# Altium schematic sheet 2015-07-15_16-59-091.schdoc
size 405 x 220 mm; SheetNumber: 1; SheetTotal: 1
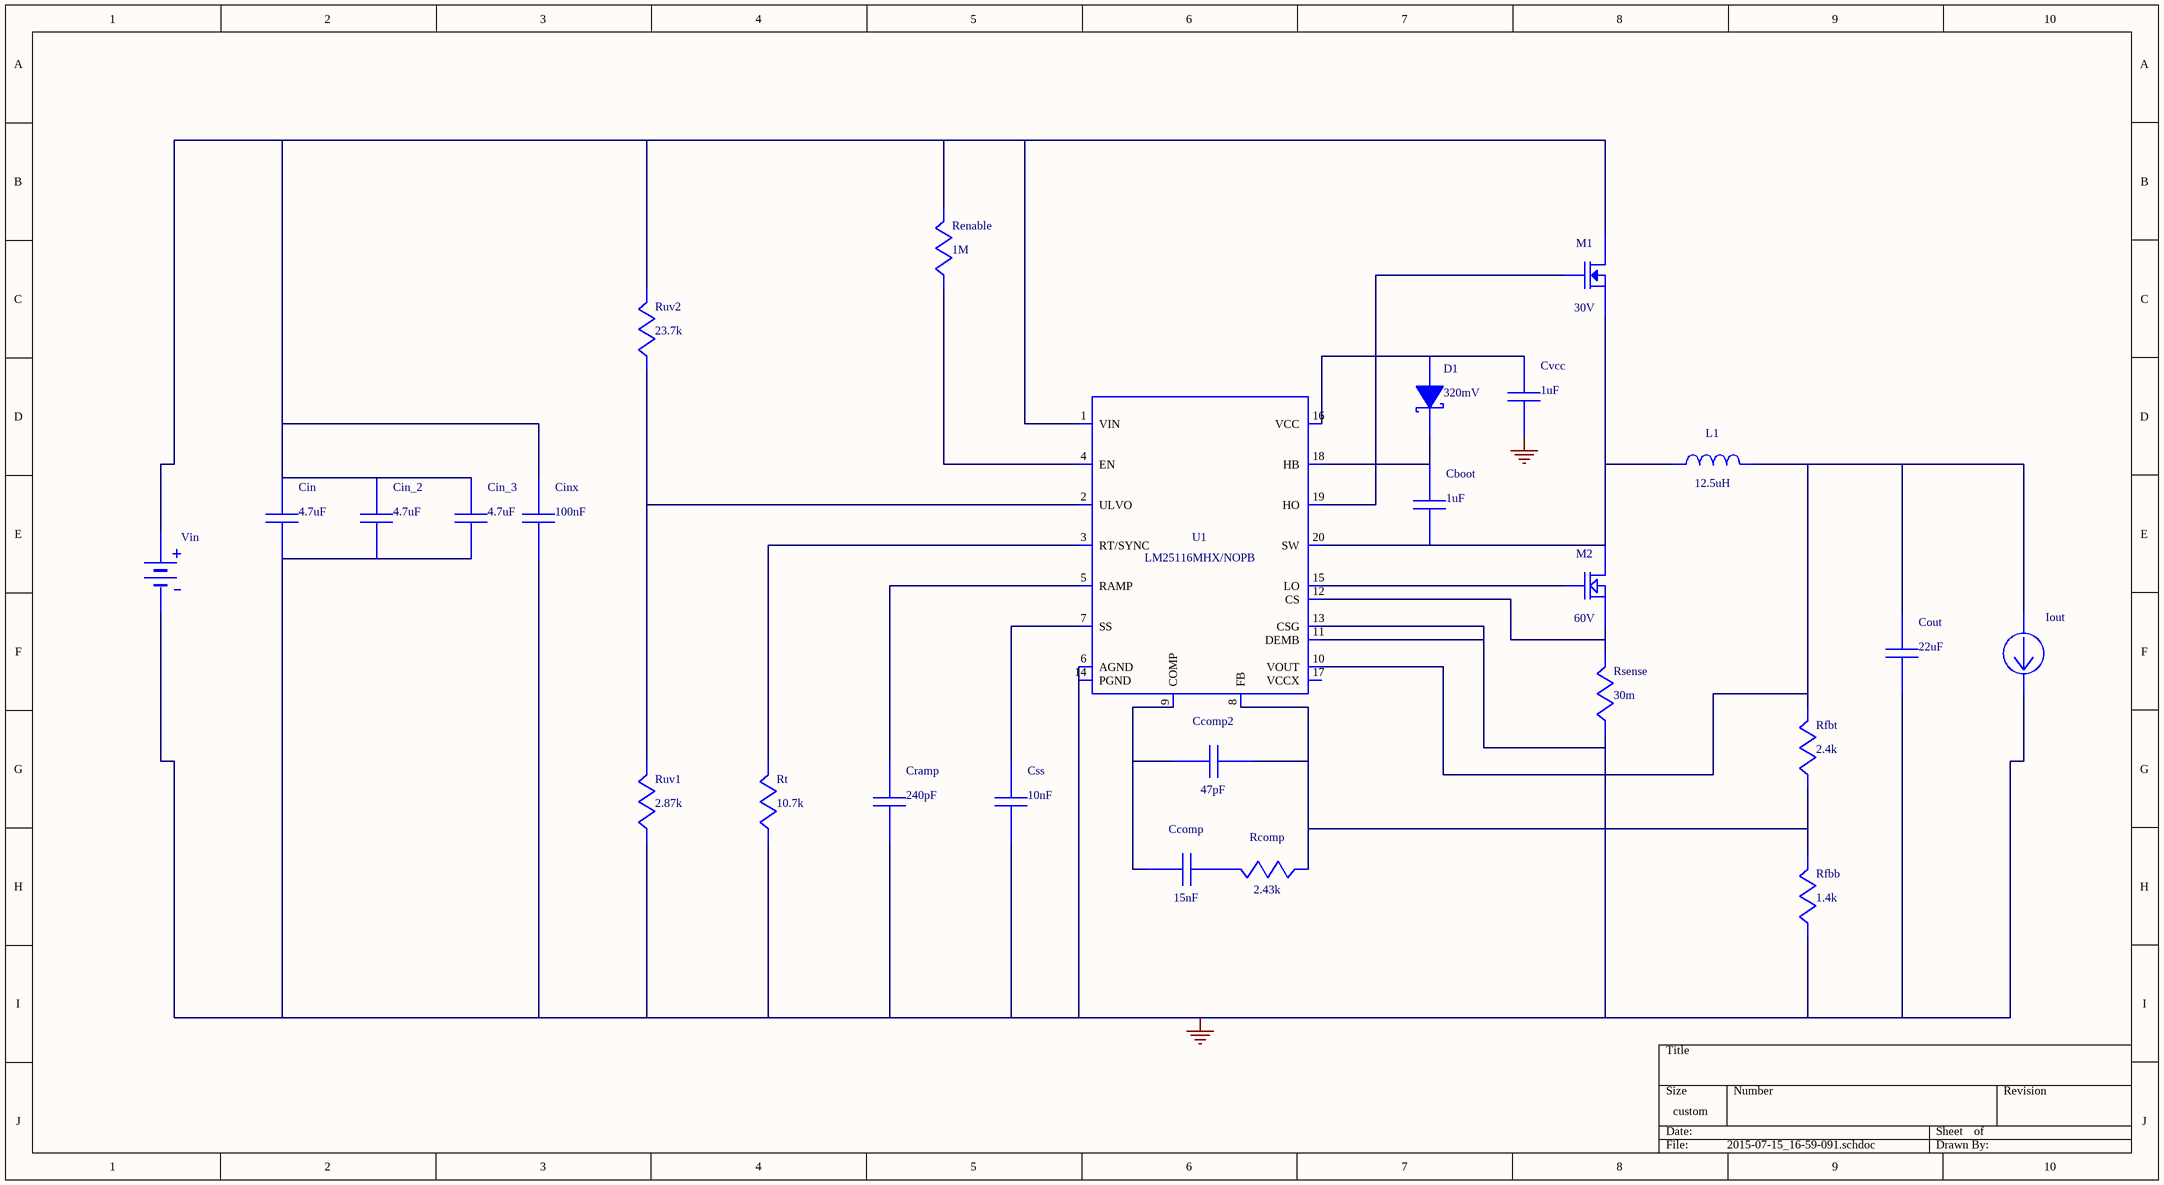
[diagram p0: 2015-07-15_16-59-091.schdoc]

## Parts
Cboot  value 1uF  (hidden comment: GRM21BR61C105KA01L)
Ccomp  value 15nF  (hidden comment: CC0805KRX7R9BB153)
Ccomp2  value 47pF  (hidden comment: C0805C470K5GACTU)
Cin  value 4.7uF  (hidden comment: GRM31CR71H475KA12L)
Cin_2  value 4.7uF  (hidden comment: GRM31CR71H475KA12L)
Cin_3  value 4.7uF  (hidden comment: GRM31CR71H475KA12L)
Cinx  value 100nF  (hidden comment: C0805C104K5RACTU)
Cout  value 22uF  (hidden comment: GRM21BR60J226ME39L)
Cramp  value 240pF  (hidden comment: CL21C241JBANNNC)
Css  value 10nF  (hidden comment: GRM216R71H103KA01D)
Cvcc  value 1uF  (hidden comment: GRM21BR61C105KA01L)
D1  value 320mV  (hidden comment: CMS06)
Iout  WB_CURRENT_LOAD  (value not drawn)
L1  value 12.5uH  (hidden comment: HC50-1252SMLF)
M1  value 30V  (hidden comment: CSD17507Q5A)
M2  value 60V  (hidden comment: BSC067N06LS3 G)
Rcomp  value 2.43k  (hidden comment: ERJ-6ENF2431V)
Renable  value 1M  (hidden comment: ERJ-6ENF1004V)
Rfbb  value 1.4k  (hidden comment: ERJ-6ENF1401V)
Rfbt  value 2.4k  (hidden comment: RR1220P-242-D)
Rsense  value 30m  (hidden comment: CSR1206FK30L0)
Rt  value 10.7k  (hidden comment: ERJ-6ENF1072V)
Ruv1  value 2.87k  (hidden comment: ERJ-6ENF2871V)
Ruv2  value 23.7k  (hidden comment: ERJ-6ENF2372V)
U1  LM25116MHX/NOPB
Vin  WB_BATTERY  (value not drawn)

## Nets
0: Cin.2 Cin_2.2 Cin_3.2 Cinx.2 Cout.2 Cramp.2 Css.2 Cvcc.2 Iout.2(-) Rfbb.2 Rsense.2 Rt.2 Ruv1.2 U1.6(AGND) U1.11(DEMB) U1.13(CSG) U1.14(PGND) U1.21(EP) Vin.2(-)
NetCboot_1: Cboot.1 D1.1(K) U1.18(HB)
NetCboot_2: Cboot.2 L1.1 M1.1(Source) M1.2(Source) M1.3(Source) M2.5(Drain) M2.6(Drain) M2.7(Drain) M2.8(Drain) M2.9(Drain) U1.20(SW)
NetCcomp2_2: Ccomp2.2 Rcomp.2 Rfbb.1 Rfbt.2 U1.8(FB)
NetCcomp_1: Ccomp.1 Ccomp2.1 U1.9(COMP)
NetCcomp_2: Ccomp.2 Rcomp.1
NetCin_1: Cin.1 Cin_2.1 Cin_3.1 Cinx.1 M1.5(Drain) M1.6(Drain) M1.7(Drain) M1.8(Drain) M1.9(Drain) Renable.1 Ruv2.1 U1.1(VIN) Vin.1(+)
NetCout_1: Cout.1 Iout.1(+) L1.2 Rfbt.1 U1.10(VOUT)
NetCramp_1: Cramp.1 U1.5(RAMP)
NetCss_1: Css.1 U1.7(SS)
NetCvcc_1: Cvcc.1 D1.2(A) U1.16(VCC)
NetM1_4: M1.4(Gate) U1.19(HO)
NetM2_1: M2.1(Source) M2.2(Source) M2.3(Source) Rsense.1 U1.12(CS)
NetM2_4: M2.4(Gate) U1.15(LO)
NetRenable_2: Renable.2 U1.4(EN)
NetRt_1: Rt.1 U1.3(RT/SYNC)
NetRuv1_1: Ruv1.1 Ruv2.2 U1.2(ULVO)

Not connected (* = marked no-connect by the designer): U1 17(VCCX)

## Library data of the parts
Cboot Cvcc = GRM21BR61C105KA01L: GRM21BR61C105KA0; Manufacturer Name: MuRata
Ccomp = CC0805KRX7R9BB153: CC0805KRX7R9BB15; Manufacturer Name: Yageo America
Ccomp2 = C0805C470K5GACTU: Manufacturer Name: Kemet
Cin Cin_2 Cin_3 = GRM31CR71H475KA12L: GRM31CR71H475KA1; Manufacturer Name: MuRata
Cinx = C0805C104K5RACTU: Manufacturer Name: Kemet
Cout = GRM21BR60J226ME39L: GRM21BR60J226ME3; Manufacturer Name: MuRata
Cramp = CL21C241JBANNNC: Manufacturer Name: Samsung Electro-Mechanics
Css = GRM216R71H103KA01D: GRM216R71H103KA0; Manufacturer Name: MuRata
D1 = CMS06: Manufacturer Name: Toshiba
Iout = WB_CURRENT_LOAD: Value: UNLISTED
L1 = HC50-1252SMLF: Manufacturer Name: GOWANDA
M1 = CSD17507Q5A: Manufacturer Name: Texas Instruments
M2 = BSC067N06LS3 G: Manufacturer Name: Infineon Technologies
Rcomp = ERJ-6ENF2431V: Manufacturer Name: Panasonic
Renable = ERJ-6ENF1004V: Manufacturer Name: Panasonic
Rfbb = ERJ-6ENF1401V: Manufacturer Name: Panasonic
Rfbt = RR1220P-242-D: Manufacturer Name: Susumu Co Ltd
Rsense = CSR1206FK30L0: Manufacturer Name: Stackpole Electronics Inc
Rt = ERJ-6ENF1072V: Manufacturer Name: Panasonic
Ruv1 = ERJ-6ENF2871V: Manufacturer Name: Panasonic
Ruv2 = ERJ-6ENF2372V: Manufacturer Name: Panasonic
U1 = LM25116MHX/NOPB: Manufacturer Name: Texas Instruments; Value: UNLISTED
Vin = WB_BATTERY: Value: UNLISTED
